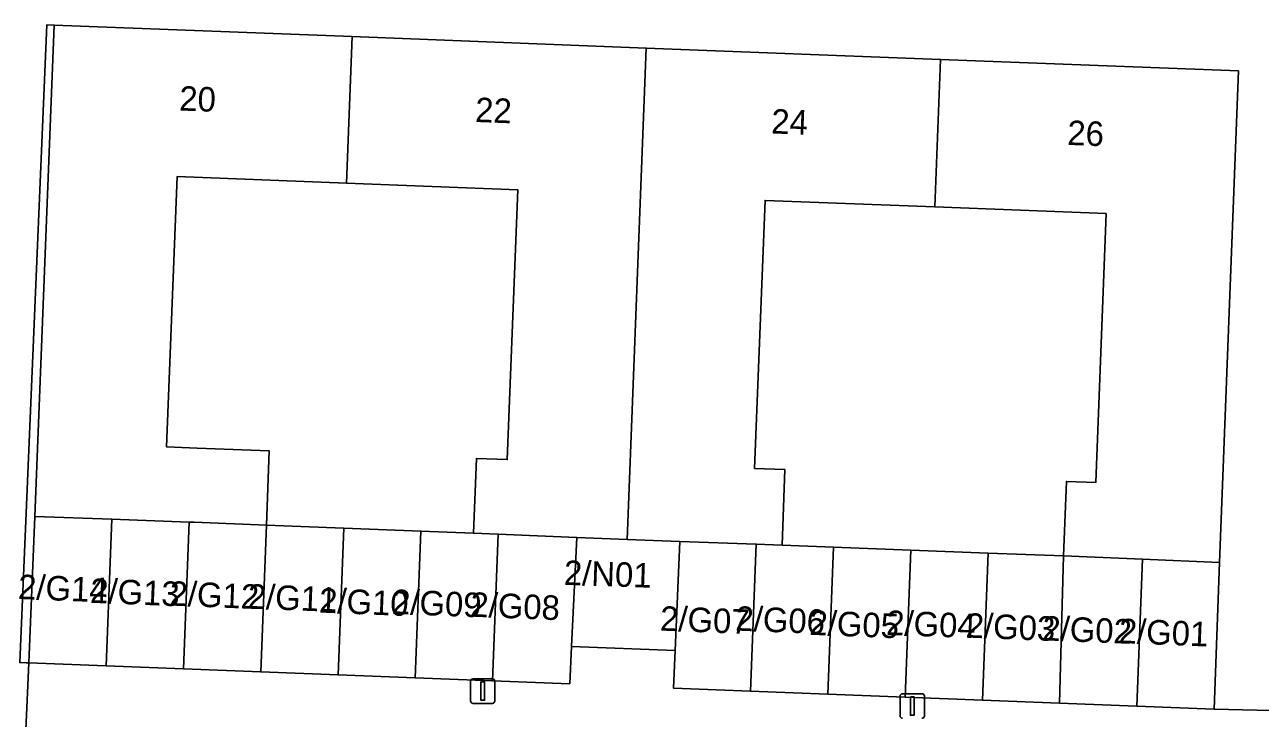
# Model space of a CAD drawing. Extents: x 160786 to 161429, y 386828 to 387485.
# Drawn here: x 161182.4 to 161232.7, y 387121.8 to 387150.1 of the extents above; entities that cross this region are included whole.
import ezdxf

# ---------------------------------------------------------------- set-up
doc = ezdxf.new("R2010")
doc.units = 0
for name, color, linetype in [('IMGEO_Erf', 7, 'Continuous'), ('IMGEO_Groenvoorziening', 7, 'Continuous'), ('IMGEO_Lichtmast', 7, 'Continuous'), ('IMGEO_Pand', 7, 'Continuous'), ('IMGEO_Pand_nummerreeks', 7, 'Continuous'), ('IMGEO_Rijbaan_lokaal_open', 7, 'Continuous'), ('IMGEO_Voetpad_open', 7, 'Continuous')]:
    doc.layers.add(name, color=color, linetype=linetype)

msp = doc.modelspace()

# ---------------------------------------------------------------- linework, layer by layer
at = {"layer": 'IMGEO_Erf'}
for points in [[(161202.447, 387143.376), (161195.469, 387143.647), (161188.572, 387143.914), (161188.144, 387132.89), (161189.388, 387132.842), (161192.328, 387132.728), (161192.211, 387129.705), (161195.359, 387129.583), (161198.506, 387129.461), (161200.646, 387129.378), (161200.764, 387132.423), (161202.021, 387132.374)], [(161224.683, 387128.446), (161224.801, 387131.486), (161225.997, 387131.439), (161226.422, 387142.407), (161219.441, 387142.677), (161212.526, 387142.945), (161212.102, 387132.012), (161213.337, 387131.964), (161213.218, 387128.89), (161215.317, 387128.809), (161218.464, 387128.687), (161221.61, 387128.565)]]:
    msp.add_lwpolyline(points, close=True, dxfattribs=at)
at = {"layer": 'IMGEO_Groenvoorziening'}
msp.add_lwpolyline([(161182.773, 387130.058), (161183.565, 387150.089), (161183.265, 387150.107), (161182.164, 387124.098), (161182.425, 387124.09), (161182.537, 387124.086)], close=True, dxfattribs=at)
at = {"layer": 'IMGEO_Lichtmast'}
for p, q in [((161200.527, 387122.536), (161200.527, 387123.336)), ((161200.527, 387123.336), (161200.527, 387122.536)), ((161200.627, 387123.436), (161201.417, 387123.436)), ((161201.417, 387123.436), (161200.627, 387123.436)), ((161201.517, 387123.336), (161201.517, 387122.536)), ((161201.517, 387122.536), (161201.517, 387123.336)), ((161218.028, 387121.925), (161218.028, 387122.725)), ((161218.028, 387122.725), (161218.028, 387121.925)), ((161218.128, 387122.825), (161218.918, 387122.825)), ((161218.918, 387122.825), (161218.128, 387122.825)), ((161219.018, 387122.725), (161219.018, 387121.925)), ((161219.018, 387121.925), (161219.018, 387122.725)), ((161201.417, 387122.436), (161200.627, 387122.436)), ((161200.627, 387122.436), (161201.417, 387122.436))]:
    msp.add_line(p, q, dxfattribs=at)
for points in [[(161200.947, 387123.311), (161201.097, 387123.311), (161201.097, 387122.561), (161200.947, 387122.561), (161200.947, 387123.311)], [(161218.448, 387122.7), (161218.598, 387122.7), (161218.598, 387121.95), (161218.448, 387121.95), (161218.448, 387122.7)]]:
    msp.add_lwpolyline(points, dxfattribs=at)
for centre, start, end in [((161200.627, 387123.336), 90, 180), ((161200.627, 387123.336), 90, 180), ((161201.417, 387123.336), 0, 90), ((161201.417, 387123.336), 360, 90), ((161200.627, 387122.536), 180, 270), ((161200.627, 387122.536), 180, 270), ((161201.417, 387122.536), 270, 0), ((161201.417, 387122.536), 270, 0), ((161218.128, 387122.725), 90, 180), ((161218.128, 387122.725), 90, 180), ((161218.918, 387122.725), 0, 90), ((161218.918, 387122.725), 360, 90), ((161218.128, 387121.925), 180, 270), ((161218.128, 387121.925), 180, 270), ((161218.918, 387121.925), 270, 0), ((161218.918, 387121.925), 270, 0)]:
    msp.add_arc(centre, 0.1, start, end, dxfattribs=at)
at = {"layer": 'IMGEO_Pand'}
for points in [[(161195.701, 387149.619), (161183.565, 387150.089), (161182.773, 387130.058), (161185.916, 387129.942), (161189.064, 387129.827), (161189.271, 387129.819), (161192.211, 387129.705), (161192.328, 387132.728), (161189.388, 387132.842), (161188.144, 387132.89), (161188.572, 387143.914), (161195.469, 387143.647)], [(161206.911, 387129.116), (161207.688, 387149.154), (161195.701, 387149.619), (161195.469, 387143.647), (161202.447, 387143.376), (161202.021, 387132.374), (161200.764, 387132.423), (161200.646, 387129.378), (161201.653, 387129.334), (161204.856, 387129.196)], [(161209.051, 387129.032), (161212.17, 387128.926), (161213.218, 387128.89), (161213.337, 387131.964), (161212.102, 387132.012), (161212.526, 387142.945), (161219.441, 387142.677), (161219.674, 387148.689), (161207.688, 387149.154), (161206.911, 387129.116)], [(161231.809, 387148.219), (161219.674, 387148.689), (161219.441, 387142.677), (161226.422, 387142.407), (161225.997, 387131.439), (161224.801, 387131.486), (161224.683, 387128.446), (161227.903, 387128.308), (161231.045, 387128.173)], [(161182.537, 387124.086), (161185.684, 387123.964), (161185.916, 387129.942), (161182.773, 387130.058)], [(161188.832, 387123.842), (161189.064, 387129.827), (161185.916, 387129.942), (161185.684, 387123.964)], [(161189.271, 387129.819), (161189.064, 387129.827), (161188.832, 387123.842), (161191.979, 387123.72), (161192.211, 387129.705)], [(161192.211, 387129.705), (161191.979, 387123.72), (161195.127, 387123.598), (161195.359, 387129.583)], [(161195.359, 387129.583), (161195.127, 387123.598), (161198.274, 387123.476), (161198.506, 387129.461)], [(161198.506, 387129.461), (161198.274, 387123.476), (161201.422, 387123.354), (161201.653, 387129.334), (161200.646, 387129.378)], [(161204.856, 387129.196), (161201.653, 387129.334), (161201.422, 387123.354), (161204.569, 387123.232), (161204.642, 387124.756)], [(161209.051, 387129.032), (161206.911, 387129.116), (161204.856, 387129.196), (161204.642, 387124.756), (161208.858, 387124.593)], [(161208.858, 387124.593), (161208.791, 387123.056), (161211.938, 387122.934), (161212.17, 387128.926), (161209.051, 387129.032)], [(161213.218, 387128.89), (161212.17, 387128.926), (161211.938, 387122.934), (161215.084, 387122.812), (161215.317, 387128.809)], [(161215.317, 387128.809), (161215.084, 387122.812), (161218.231, 387122.69), (161218.464, 387128.687)], [(161218.464, 387128.687), (161218.231, 387122.69), (161221.378, 387122.568), (161221.61, 387128.565)], [(161221.61, 387128.565), (161221.378, 387122.568), (161224.525, 387122.446), (161224.683, 387128.446)], [(161227.903, 387128.308), (161224.683, 387128.446), (161224.525, 387122.446), (161227.671, 387122.324)], [(161230.818, 387122.202), (161231.045, 387128.173), (161227.903, 387128.308), (161227.671, 387122.324)]]:
    msp.add_lwpolyline(points, close=True, dxfattribs=at)
at = {"layer": 'IMGEO_Rijbaan_lokaal_open'}
msp.add_lwpolyline([(161233.72, 387122.137), (161230.818, 387122.202), (161227.671, 387122.324), (161224.525, 387122.446), (161221.378, 387122.568), (161218.231, 387122.69), (161215.084, 387122.812), (161211.938, 387122.934), (161208.791, 387123.056), (161208.858, 387124.593), (161204.642, 387124.756), (161204.569, 387123.232), (161201.422, 387123.354), (161198.274, 387123.476), (161195.127, 387123.598), (161191.979, 387123.72), (161188.832, 387123.842), (161185.684, 387123.964), (161182.537, 387124.086), (161182.029, 387112.851)], dxfattribs=at)
at = {"layer": 'IMGEO_Voetpad_open'}
msp.add_lwpolyline([(161182.029, 387112.851), (161182.537, 387124.086), (161182.425, 387124.09), (161182.164, 387124.098), (161183.265, 387150.107), (161183.565, 387150.089), (161195.701, 387149.619), (161207.688, 387149.154), (161219.674, 387148.689), (161231.809, 387148.219), (161231.045, 387128.173), (161230.818, 387122.202), (161233.72, 387122.137)], dxfattribs=at)

# ---------------------------------------------------------------- texts
at = {"layer": 'IMGEO_Pand_nummerreeks'}
for s, rotation, p in [('20', 357.7827, (161188.646, 387146.609)), ('22', 357.7803, (161200.701, 387146.142)), ('24', 357.7803, (161212.765, 387145.674)), ('26', 357.7803, (161224.826, 387145.207)), ('2/N01', 358.085, (161204.318, 387127.268)), ('2/G14', 357.7067, (161182.079, 387126.693)), ('2/G13', 357.7067, (161185.015, 387126.537)), ('2/G12', 357.7067, (161188.249, 387126.423)), ('2/G11', 357.7067, (161191.436, 387126.305)), ('2/G10', 357.7067, (161194.342, 387126.138)), ('2/G09', 357.7067, (161197.315, 387126.085)), ('2/G08', 357.7067, (161200.505, 387125.971)), ('2/G07', 357.7067, (161208.235, 387125.403)), ('2/G06', 357.7067, (161211.305, 387125.403)), ('2/G05', 357.7067, (161214.319, 387125.232)), ('2/G04', 357.7067, (161217.446, 387125.232)), ('2/G03', 357.7067, (161220.687, 387125.119)), ('2/G02', 357.7067, (161223.808, 387125.005)), ('2/G01', 357.7067, (161226.922, 387124.897))]:
    msp.add_text(s, height=1, rotation=rotation, dxfattribs=at).set_placement(p)

doc.saveas('drawing.dxf')
